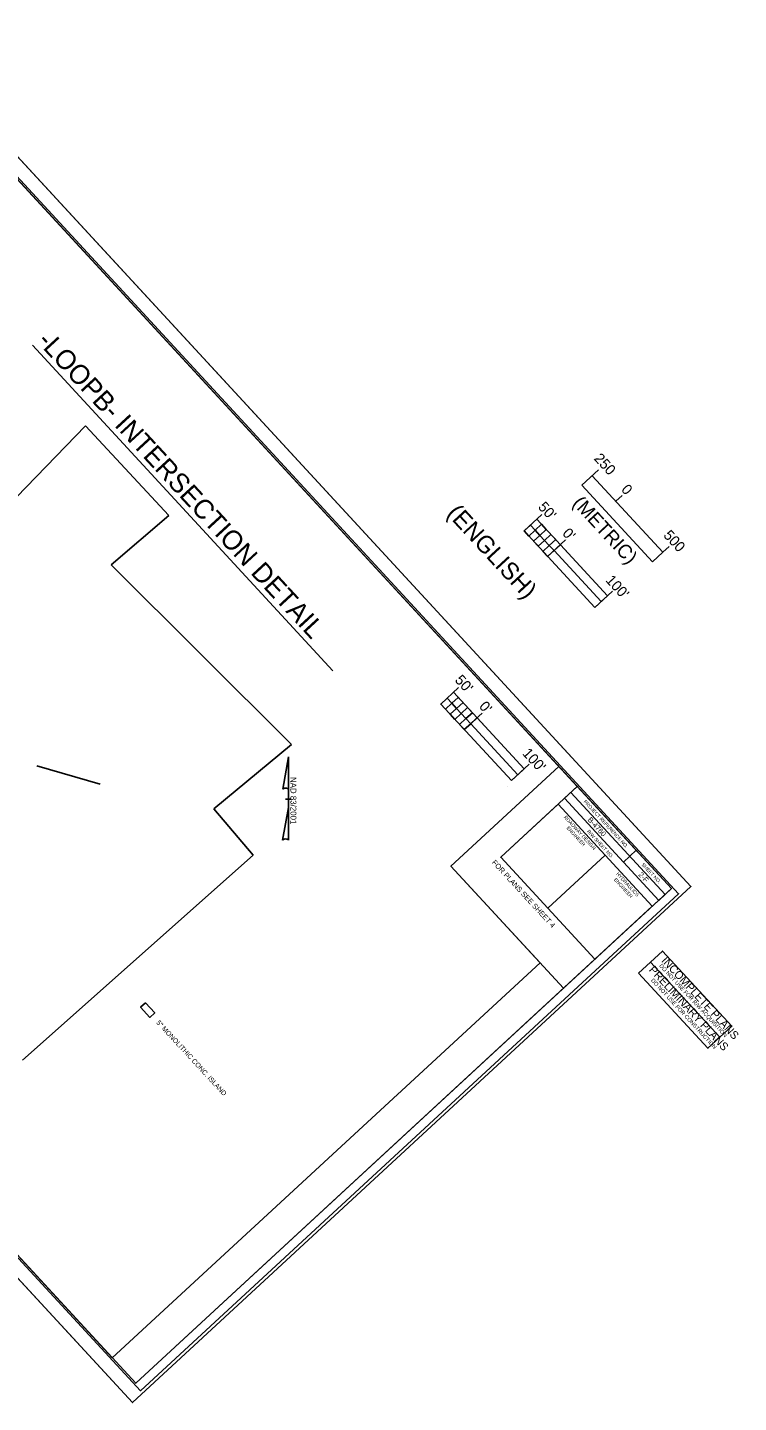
# Model space of a CAD drawing. Extents: x 1702195 to 1704210, y 794290 to 796270.
# Drawn here: x 1703186 to 1704210, y 794290 to 796270 of the extents above; entities that cross this region are included whole.
import ezdxf

# ---------------------------------------------------------------- set-up
doc = ezdxf.new("R2010")
doc.units = 0
for name, color, linetype in [('Prop Conc 5in Monolithic Surface Mount Island', 7, 'Continuous'), ('Prop Horizontal Alignment Curve and Spiral Data', 7, 'Continuous'), ('Prop Horizontal Alignment Station Label', 7, 'Continuous'), ('Prop North Arrow NAD83 for Plan Sheets CELL', 7, 'Continuous'), ('Prop PHM English Scale CELL', 7, 'Continuous'), ('Prop PHM Metric Scale CELL', 7, 'Continuous'), ('Sheet Clip Boundary CELL', 7, 'Continuous'), ('Sheet Cutting Line CELL', 7, 'Continuous'), ('Sheet Data Field CELL', 7, 'Continuous'), ('Sheet Layout Plan Border', 7, 'Continuous'), ('Sheet North Arrow Point CELL', 7, 'Continuous'), ('Sheet Plan CELL', 7, 'Continuous'), ('Sheet Plan Layout CELL', 7, 'Continuous'), ('Sheet Plot Border Inside CELL', 7, 'Continuous'), ('Sheet Plot Border Outside CELL', 7, 'Continuous'), ('Sheet Sticker Incomplete CELL', 7, 'Continuous'), ('Sheet Sticker Preliminary CELL', 7, 'Continuous')]:
    doc.layers.add(name, color=color, linetype=linetype)

msp = doc.modelspace()

# ---------------------------------------------------------------- linework, layer by layer
at = {"layer": 'Prop Conc 5in Monolithic Surface Mount Island'}
msp.add_lwpolyline([(1703356, 794865.9), (1703369.5, 794851.3), (1703362.5, 794844.8), (1703349, 794859.5)], close=True, dxfattribs=at)
at = {"layer": 'Prop Horizontal Alignment Curve and Spiral Data'}
msp.add_line((1703193.4, 795812.7), (1703626, 795344.1), dxfattribs=at)
at = {"layer": 'Prop North Arrow NAD83 for Plan Sheets CELL'}
for p, q in [((1703553.8, 795173.5), (1703562, 795219.9)), ((1703562, 795219.9), (1703562, 795219.9)), ((1703562, 795219.9), (1703562, 795219.9)), ((1703562, 795219.9), (1703562, 795172.1)), ((1703562, 795147.3), (1703562, 795173.5)), ((1703562, 795172.1), (1703562, 795173.4)), ((1703561.6, 795158.9), (1703558, 795158.9)), ((1703558, 795158.9), (1703558, 795158.9)), ((1703558.1, 795158.9), (1703566.1, 795158.9)), ((1703562, 795147.3), (1703553.7, 795100)), ((1703562.1, 795100.2), (1703562, 795147.3))]:
    msp.add_line(p, q, dxfattribs=at)
for centre, start_param, end_param in [((1703557.9, 795173), 0.216388, 2.908219), ((1703557.9, 795099.9), 0.201328, 3.141593)]:
    msp.add_ellipse(centre, major_axis=(4.23, -0.03), ratio=0.461098, start_param=start_param, end_param=end_param, dxfattribs=at)
at = {"layer": 'Prop PHM English Scale CELL'}
for p, q in [((1703927.2, 795569), (1703901.5, 795545.3)), ((1704021.6, 795452), (1703919.9, 795562.2)), ((1703901.5, 795545.3), (1704003.2, 795435)), ((1703961.1, 795532.3), (1703935.4, 795508.5)), ((1703962.6, 795533.6), (1703962.6, 795533.6)), ((1704029, 795458.8), (1704003.2, 795435)), ((1704003.2, 795435), (1704021.6, 795452)), ((1704030.4, 795460.1), (1704030.4, 795460.1)), ((1703807.2, 795319.8), (1703781.5, 795296)), ((1703901.6, 795202.8), (1703799.9, 795313)), ((1703781.5, 795296), (1703883.3, 795185.8)), ((1703841.2, 795283), (1703815.4, 795259.3)), ((1703842.6, 795284.4), (1703842.6, 795284.4)), ((1703910.4, 795210.9), (1703910.4, 795210.9)), ((1703909, 795209.6), (1703883.3, 795185.8)), ((1703883.3, 795185.8), (1703901.6, 795202.8))]:
    msp.add_line(p, q, dxfattribs=at)
at = {"layer": 'Prop PHM Metric Scale CELL'}
for p, q in [((1703984.8, 795611.3), (1704008.7, 795633.3)), ((1704086.6, 795501), (1703984.8, 795611.3)), ((1703999.5, 795624.8), (1704101.4, 795514.6)), ((1704042.7, 795596.6), (1704033.5, 795588.1)), ((1704101.4, 795514.6), (1704086.6, 795501)), ((1704110.5, 795523), (1704101.4, 795514.6))]:
    msp.add_line(p, q, dxfattribs=at)
for points in [[(1703917.5, 795546.4), (1703910.7, 795553.7), (1703901.5, 795545.3), (1703908.3, 795537.9)], [(1703917.5, 795546.4), (1703910.7, 795553.7), (1703901.5, 795545.3), (1703908.3, 795537.9)], [(1703924.2, 795539), (1703917.5, 795546.4), (1703926.6, 795554.9), (1703933.4, 795547.5)], [(1703933.4, 795547.5), (1703926.6, 795554.9), (1703917.5, 795546.4), (1703924.2, 795539)], [(1703931, 795531.7), (1703924.2, 795539), (1703915.1, 795530.6), (1703921.8, 795523.2)], [(1703947, 795532.8), (1703940.2, 795540.2), (1703931, 795531.7), (1703937.8, 795524.3)], [(1703944.6, 795517), (1703937.8, 795524.3), (1703928.6, 795515.9), (1703935.4, 795508.5)], [(1704021.6, 795452), (1703953.8, 795525.5), (1703944.6, 795517), (1704012.4, 795443.5)], [(1703797.5, 795297.2), (1703790.7, 795304.5), (1703781.5, 795296), (1703788.3, 795288.7)], [(1703797.5, 795297.2), (1703790.7, 795304.5), (1703781.5, 795296), (1703788.3, 795288.7)], [(1703811, 795282.5), (1703804.3, 795289.8), (1703795.1, 795281.4), (1703801.9, 795274)], [(1703804.3, 795289.8), (1703797.5, 795297.2), (1703806.7, 795305.7), (1703813.5, 795298.3)], [(1703813.5, 795298.3), (1703806.7, 795305.7), (1703797.5, 795297.2), (1703804.3, 795289.8)], [(1703827, 795283.6), (1703820.2, 795291), (1703811, 795282.5), (1703817.8, 795275.1)], [(1703824.6, 795267.8), (1703817.8, 795275.1), (1703808.6, 795266.7), (1703815.4, 795259.3)], [(1703901.6, 795202.8), (1703833.8, 795276.3), (1703824.6, 795267.8), (1703892.4, 795194.3)]]:
    msp.add_lwpolyline(points, close=True, dxfattribs=at)
at = {"layer": 'Sheet Clip Boundary CELL'}
for p, q in [((1703269.8, 795696.6), (1702989.4, 795407.6)), ((1703389.9, 795567.6), (1703269.8, 795696.6)), ((1703306.5, 795496.7), (1703389.9, 795567.6)), ((1703566.4, 795237.8), (1703306.5, 795496.7)), ((1703454.5, 795145), (1703566.4, 795237.8)), ((1703511.3, 795078.4), (1703454.5, 795145)), ((1703178.9, 794783.1), (1703511.3, 795078.4))]:
    msp.add_line(p, q, dxfattribs=at)
msp.add_lwpolyline([(1702358.7, 795383.7), (1703308.3, 794354.9), (1703924.5, 794923.7), (1703796.1, 795062.8), (1703951.5, 795206.2), (1703130.3, 796095.9)], close=True, dxfattribs=at)
at = {"layer": 'Sheet Cutting Line CELL'}
for p, q in [((1704141.8, 795033.2), (1703000, 796270.2)), ((1702195.3, 795527.5), (1703337.2, 794290.4))]:
    msp.add_line(p, q, dxfattribs=at)
at = {"layer": 'Sheet Layout Plan Border'}
msp.add_lwpolyline([(1702358.7, 795383.7), (1703308.3, 794354.9), (1703924.5, 794923.7), (1703796.1, 795062.8), (1703951.5, 795206.2), (1703130.3, 796095.9)], close=True, dxfattribs=at)
at = {"layer": 'Sheet North Arrow Point CELL'}
msp.add_line((1703878.3, 795177.9), (1703878.3, 795177.9), dxfattribs=at)
at = {"layer": 'Sheet Plan CELL'}
for p, q in [((1703291, 795180.7), (1703199.8, 795207.1)), ((1703959.7, 795160.4), (1703950.5, 795151.9)), ((1703959.7, 795160.4), (1704095.4, 795013.4)), ((1703959.7, 795160.4), (1704095.4, 795013.4)), ((1703968.9, 795168.9), (1704104.5, 795021.9)), ((1704018.3, 795078.4), (1703935.7, 795002.1)), ((1704062.8, 795085.5), (1704044.5, 795068.5))]:
    msp.add_line(p, q, dxfattribs=at)
for points in [[(1704113.8, 795030.4), (1703096.4, 796132.6), (1702324.8, 795420.4), (1703342.2, 794318.2)], [(1702324.8, 795420.4), (1703096.3, 796132.6), (1703978.1, 795177.4), (1703867.8, 795075.6), (1704003.5, 794928.6), (1703342.2, 794318.2)], [(1703978.1, 795177.4), (1704113.8, 795030.4), (1704095.4, 795013.4), (1703959.7, 795160.4)], [(1703950.5, 795151.9), (1704018.3, 795078.4), (1703935.7, 795002.1), (1703867.8, 795075.6)], [(1704018.3, 795078.4), (1704086.2, 795004.9), (1704003.5, 794928.6), (1703935.7, 795002.1)]]:
    msp.add_lwpolyline(points, close=True, dxfattribs=at)
at = {"layer": 'Sheet Plan Layout CELL'}
for points in [[(1703096.3, 796132.6), (1702324.8, 795420.4), (1703342.2, 794318.2), (1703958.4, 794887), (1703796.1, 795062.8), (1703951.5, 795206.2)], [(1703796.1, 795062.8), (1703958.4, 794886.9), (1704113.8, 795030.4), (1703951.5, 795206.2)]]:
    msp.add_lwpolyline(points, close=True, dxfattribs=at)
at = {"layer": 'Sheet Plot Border Inside CELL'}
msp.add_lwpolyline([(1702218.9, 795531.5), (1703348.9, 794307.3), (1704124.1, 795022.9), (1702994.1, 796247.1)], close=True, dxfattribs=at)
at = {"layer": 'Sheet Plot Border Outside CELL'}
msp.add_lwpolyline([(1702195.3, 795527.5), (1703337.2, 794290.4), (1704141.8, 795033.2), (1703000, 796270.2)], close=True, dxfattribs=at)
at = {"layer": 'Sheet Sticker Incomplete CELL'}
msp.add_lwpolyline([(1704083.8, 794924.6), (1704101.1, 794940.5), (1704200.8, 794832.5), (1704183.5, 794816.5)], close=True, dxfattribs=at)
at = {"layer": 'Sheet Sticker Preliminary CELL'}
msp.add_lwpolyline([(1704066.5, 794908.6), (1704083.8, 794924.6), (1704183.5, 794816.5), (1704166.2, 794800.6)], close=True, dxfattribs=at)

# ---------------------------------------------------------------- texts
at = {"layer": 'Prop Horizontal Alignment Curve and Spiral Data'}
msp.add_text('-LOOPB- INTERSECTION DETAIL', height=28, rotation=312.7091, dxfattribs=at).set_placement((1703198.8, 795817.7))
at = {"layer": 'Prop Horizontal Alignment Station Label'}
msp.add_text('FOR PLANS SEE SHEET 4', height=7.5, rotation=312.7091, dxfattribs=at).set_placement((1703854.6, 795067.5))
at = {"layer": 'Prop North Arrow NAD83 for Plan Sheets CELL'}
msp.add_text('NAD 83/2001', height=8.5, rotation=270, dxfattribs=at).set_placement((1703565, 795191.1))
at = {"layer": 'Prop PHM English Scale CELL'}
for s, height, p in [("50'", 15, (1703920.7, 795579)), ('(ENGLISH)', 25, (1703789, 795569.5)), (" 0'", 15, (1703951.9, 795545.2)), ("100'", 15, (1704018, 795473.6)), ("50'", 15, (1703800.8, 795329.8)), (" 0'", 15, (1703831.9, 795296)), ("100'", 15, (1703898, 795224.4))]:
    msp.add_text(s, height=height, rotation=312.7091, dxfattribs=at).set_placement(p)
at = {"layer": 'Prop PHM Metric Scale CELL'}
for s, height, p in [('250', 15.01, (1704001.2, 795648.9)), ('0', 15, (1704040.5, 795604.1)), ('(METRIC)', 20.01, (1703970.2, 795584.3)), ('500', 15.01, (1704101.3, 795538.2))]:
    msp.add_text(s, height=height, rotation=312.7091, dxfattribs=at).set_placement(p)
at = {"layer": 'Sheet Data Field CELL'}
for s, p in [('B-4760', (1703992.3, 795129.1)), ('2-F', (1704065.5, 795049.9))]:
    msp.add_text(s, height=7.5, rotation=312.7091, dxfattribs=at).set_placement(p)
at = {"layer": 'Sheet Plan CELL'}
for s, height, p in [('PROJECT REFERENCE NO.', 5, (1703986.7, 795155.2)), ('ROADWAY DESIGN', 5, (1703958.3, 795132.7)), ('ENGINEER', 5, (1703962.2, 795117.3)), ('R/W SHEET NO.', 5, (1703991.6, 795112.3)), ('HYDRAULICS', 5, (1704033.7, 795051.1)), ('SHEET NO.', 5, (1704070.2, 795064.6)), ('ENGINEER', 5, (1704030.4, 795042.9)), ('5" MONOLITHIC CONC. ISLAND', 7, (1703371.2, 794836.8))]:
    msp.add_text(s, height=height, rotation=312.7091, dxfattribs=at).set_placement(p)
at = {"layer": 'Sheet Sticker Incomplete CELL'}
for s, height, p in [('DO NOT USE FOR R/W ACQUISITION', 5.76, (1704095.6, 794918.8)), ('INCOMPLETE PLANS', 11.52, (1704098.5, 794925.9))]:
    msp.add_text(s, height=height, rotation=312.7091, dxfattribs=at).set_placement(p)
at = {"layer": 'Sheet Sticker Preliminary CELL'}
for s, height, p in [('PRELIMINARY PLANS', 11.52, (1704080.6, 794912.8)), ('DO NOT USE FOR CONSTRUCTION', 5.76, (1704083.8, 794897.9))]:
    msp.add_text(s, height=height, rotation=312.7091, dxfattribs=at).set_placement(p)

doc.saveas('drawing.dxf')
